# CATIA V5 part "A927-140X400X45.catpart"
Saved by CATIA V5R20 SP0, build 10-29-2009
Part number: A927-140X400X45
Source: Unknown
Property "A": "90.000"
Property "ARTICLENO": "A927-140X400X45"
Property "BOMINFO": "A927-140X400X45"
Property "CODE": "A927-140X400X45"
Property "CREATOR": "CADENAS GmbH"
Property "D": "22.000"
Property "D1": "33.000"
Property "F": "36.000"
Property "FORM": "B"
Property "L": "400.000"
Property "L1": "150.000"
Property "L2": "40.000"
Property "L3": "90.000"
Property "LINA": "A927-140X400X45"
Property "NB": "A927-140X400X45"
Property "NBSYN": "$CODE."
Property "NN": "A927"
Property "NT": "VDI 3387 Removable Die Heels, steel and self-lubricating"
Property "R": "31.500"
Property "S": "45.000"
Property "SUPPLIER": "CF"
Property "T": "25.500"
Property "W": "140.000"
Bounding box of the stored display mesh (mm): x -70 to 70, y 0 to 400, z -45 to 0
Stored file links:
  C:\Users\borellobunino\Desktop\3D X SITO CF\A927\GSB_OILLESS_G2290514040045\CATIAV5\A927-140X400X45.catpart
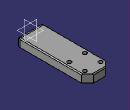
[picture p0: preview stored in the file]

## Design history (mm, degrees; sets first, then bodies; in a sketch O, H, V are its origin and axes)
Body1 "Geometry.1" (main body)
  Solid1 "A927-140X400X45.catpart": solid without history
